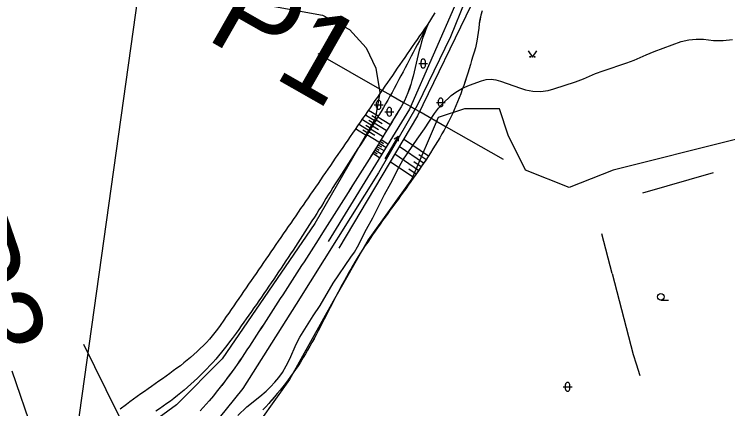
# Model space of a CAD drawing. Extents: x -737422 to -734235, y -1145631 to -1142623.
# Drawn here: x -736890.5 to -736808.9, y -1144790.3 to -1144745.2 of the extents above; entities that cross this region are included whole.
import ezdxf

# ---------------------------------------------------------------- set-up
doc = ezdxf.new("R2010")
doc.units = 0
for name, color, linetype in [('Vrstva 1', 7, 'Continuous'), ('Vrstva 2', 7, 'Continuous'), ('Vrstva 20', 7, 'Continuous'), ('Vrstva 21', 7, 'Continuous'), ('Vrstva 3', 7, 'Continuous'), ('Vrstva 30', 7, 'Continuous'), ('Vrstva 8', 7, 'Continuous'), ('Vrstva 9', 7, 'Continuous')]:
    doc.layers.add(name, color=color, linetype=linetype)

# ---------------------------------------------------------------- blocks, each defined once
blk = doc.blocks.new('3.140')
at = {"layer": 'Vrstva 1'}
blk.add_lwpolyline([(-1, 1.5), (0, 0), (1, 1.5)], dxfattribs=at)
for centre in [(-0.5, 0.1), (0.5, 0.1)]:
    blk.add_circle(centre, 0.1, dxfattribs=at)
blk = doc.blocks.new('3.040')
at = {"layer": 'Vrstva 1'}
blk.add_line((0, -0.75), (1.75, -0.75), dxfattribs=at)
blk.add_circle((0, 0), 0.75, dxfattribs=at)
blk = doc.blocks.new('3.160')
at = {"layer": 'Vrstva 1'}
for p, q in [((-1, 0), (1, 0)), ((-0.5, -0.5), (-0.5, 0.5)), ((0.5, -0.5), (0.5, 0.5))]:
    blk.add_line(p, q, dxfattribs=at)
for centre, start, end in [((0, 0.5), 0, 180), ((0, -0.5), 180, 360)]:
    blk.add_arc(centre, 0.5, start, end, dxfattribs=at)
blk = doc.blocks.new('8.021')
at = {"layer": 'Vrstva 1'}
blk.add_line((-3, 0), (3, 0), dxfattribs=at)
blk.add_lwpolyline([(2, 0.5), (3, 0), (2, -0.5)], dxfattribs=at)

msp = doc.modelspace()

# ---------------------------------------------------------------- linework, layer by layer
at = {"layer": 'Vrstva 1'}
for points in [[(-736865.99, -1144743.29), (-736855.23, -1144745.29), (-736852.15, -1144746.93), (-736850.23, -1144749.03), (-736849.12, -1144751.35), (-736848.67, -1144754.12), (-736849.21, -1144757.15), (-736856.11, -1144769.14), (-736866.72, -1144784.6), (-736871.93, -1144789.89), (-736877.86, -1144794.22), (-736879.95, -1144795.31), (-736879.05, -1144799.66), (-736881.65, -1144806.19), (-736880.62, -1144808.86), (-736878.14, -1144810.85), (-736867.34, -1144816.58), (-736863.13, -1144818.44), (-736852.07, -1144823.23), (-736841.91, -1144827.1), (-736835.16, -1144828.62)], [(-736841.958, -1144755.927), (-736841.49, -1144755.415), (-736840.497, -1144754.486), (-736839.971, -1144754.075), (-736839.207, -1144753.627), (-736838.407, -1144753.27), (-736837.061, -1144752.783), (-736836.51, -1144752.651), (-736835.949, -1144752.612), (-736835.392, -1144752.669), (-736834.85, -1144752.814), (-736832.597, -1144753.649), (-736832.009, -1144753.839), (-736831.168, -1144753.986), (-736830.29, -1144754.004), (-736829.415, -1144753.89), (-736828.777, -1144753.719), (-736826.294, -1144752.913), (-736825.368, -1144752.563), (-736824.008, -1144751.964), (-736823.144, -1144751.637), (-736820.437, -1144750.747), (-736819.574, -1144750.414), (-736818.219, -1144749.798), (-736817.297, -1144749.428), (-736814.203, -1144748.304), (-736813.338, -1144748.111), (-736812.473, -1144748.025), (-736811.647, -1144748.035), (-736810.514, -1144748.159), (-736809.955, -1144748.186), (-736809.405, -1144748.166), (-736808.351, -1144748.044)], [(-736864.924, -1144791.087), (-736863.9, -1144790.104), (-736862.389, -1144788.939), (-736861.659, -1144788.332), (-736861.16, -1144787.829), (-736860.689, -1144787.297), (-736860.232, -1144786.753), (-736859.807, -1144786.176), (-736859.365, -1144785.416), (-736858.977, -1144784.602), (-736858.242, -1144782.934), (-736857.837, -1144782.138), (-736856.286, -1144779.686), (-736855.478, -1144778.493), (-736854.01, -1144775.958), (-736851.973, -1144772.99), (-736851.575, -1144772.387), (-736851.238, -1144771.802), (-736850.188, -1144769.767), (-736849.46, -1144768.49), (-736848.146, -1144765.79), (-736847.42, -1144764.506), (-736846.429, -1144762.56), (-736846.036, -1144761.866), (-736844.41, -1144759.464), (-736843.563, -1144758.302), (-736842.415, -1144756.536), (-736841.958, -1144755.927)]]:
    msp.add_lwpolyline(points, dxfattribs=at)
at = {"layer": 'Vrstva 2'}
msp.add_lwpolyline([(-736838.94, -1144743.71), (-736840.58, -1144747.75), (-736844.39, -1144755.61), (-736848.81, -1144763.32), (-736858.24, -1144778.35), (-736864.33, -1144788), (-736868, -1144792.54), (-736868.74, -1144793.25), (-736870.42, -1144794.38), (-736872.26, -1144795.22), (-736876.13, -1144796.44), (-736887.1, -1144799.6), (-736890.46, -1144800.61), (-736895.84, -1144803.1), (-736899.26, -1144804.04), (-736901.02, -1144804.24), (-736906.35, -1144804.39), (-736912.33, -1144804.46), (-736917.21, -1144803.72), (-736923.41, -1144802.63), (-736927.55, -1144801.53), (-736932.98, -1144799.76), (-736935.72, -1144798.99), (-736947.76, -1144796.51)], dxfattribs=at)
at = {"layer": 'Vrstva 20'}
for points in [[(-736839.85, -1144743.69), (-736845.28, -1144756.03)], [(-736838.21, -1144744.12), (-736844.35, -1144756.78)], [(-736836.95, -1144744.79), (-736837.1, -1144745.27), (-736837.21, -1144745.75), (-736837.3, -1144746.25), (-736837.36, -1144746.75), (-736837.42, -1144747.25), (-736837.49, -1144747.75), (-736837.56, -1144748.25), (-736837.74, -1144749.02), (-736837.88, -1144749.5), (-736838.02, -1144749.98), (-736838.17, -1144750.46), (-736838.31, -1144750.94), (-736838.46, -1144751.42), (-736838.61, -1144751.9), (-736838.76, -1144752.37), (-736838.92, -1144752.85), (-736839.08, -1144753.32), (-736839.24, -1144753.79), (-736839.41, -1144754.27), (-736839.59, -1144754.73), (-736839.77, -1144755.2), (-736839.96, -1144755.66), (-736840.16, -1144756.12), (-736840.36, -1144756.58), (-736840.58, -1144757.03), (-736840.8, -1144757.48), (-736841.07, -1144757.99), (-736841.31, -1144758.43), (-736841.56, -1144758.87), (-736841.82, -1144759.31), (-736842.07, -1144759.74), (-736842.34, -1144760.17), (-736842.6, -1144760.59), (-736842.87, -1144761.02), (-736843.14, -1144761.44), (-736843.42, -1144761.86), (-736843.7, -1144762.27), (-736843.98, -1144762.69), (-736844.27, -1144763.1), (-736844.55, -1144763.51), (-736844.84, -1144763.92), (-736845.13, -1144764.33), (-736845.42, -1144764.74), (-736845.71, -1144765.14), (-736846.01, -1144765.55), (-736846.3, -1144765.95), (-736846.59, -1144766.36), (-736846.89, -1144766.76), (-736847.18, -1144767.17), (-736847.48, -1144767.57), (-736847.77, -1144767.98), (-736848.06, -1144768.38), (-736848.35, -1144768.79), (-736848.64, -1144769.19), (-736848.93, -1144769.6), (-736849.21, -1144770.01), (-736849.5, -1144770.42), (-736849.78, -1144770.83), (-736850.06, -1144771.24), (-736850.33, -1144771.66), (-736850.6, -1144772.08), (-736850.87, -1144772.49), (-736851.14, -1144772.92), (-736851.49, -1144773.49), (-736851.75, -1144773.92), (-736852, -1144774.35), (-736852.24, -1144774.78), (-736852.48, -1144775.22), (-736852.72, -1144775.65), (-736852.96, -1144776.09), (-736853.19, -1144776.53), (-736853.42, -1144776.98), (-736853.65, -1144777.42), (-736853.88, -1144777.86), (-736854.11, -1144778.31), (-736854.34, -1144778.75), (-736854.56, -1144779.2), (-736854.79, -1144779.64), (-736855.02, -1144780.09), (-736855.25, -1144780.53), (-736855.48, -1144780.98), (-736855.71, -1144781.42)], [(-736842.37, -1144745.01), (-736842.65, -1144745.43), (-736842.99, -1144746), (-736843.21, -1144746.45), (-736843.41, -1144746.91), (-736843.58, -1144747.37), (-736843.75, -1144747.84), (-736843.89, -1144748.32), (-736844.03, -1144748.81), (-736844.16, -1144749.3), (-736844.28, -1144749.79), (-736844.39, -1144750.28), (-736844.51, -1144750.78), (-736844.62, -1144751.27), (-736844.74, -1144751.76), (-736844.87, -1144752.25), (-736845, -1144752.74), (-736845.14, -1144753.22), (-736845.3, -1144753.69), (-736845.47, -1144754.16), (-736845.65, -1144754.62), (-736845.86, -1144755.07), (-736846.24, -1144755.77), (-736846.5, -1144756.2), (-736846.76, -1144756.63), (-736847.02, -1144757.05), (-736847.28, -1144757.48), (-736847.54, -1144757.91), (-736847.8, -1144758.34), (-736848.06, -1144758.76), (-736848.32, -1144759.19), (-736848.58, -1144759.62), (-736848.84, -1144760.04), (-736849.1, -1144760.47), (-736849.37, -1144760.89), (-736849.63, -1144761.32), (-736849.89, -1144761.74), (-736850.15, -1144762.17), (-736850.42, -1144762.59), (-736850.68, -1144763.02), (-736850.95, -1144763.44), (-736851.21, -1144763.86), (-736851.48, -1144764.29), (-736851.74, -1144764.71), (-736852.01, -1144765.14), (-736852.28, -1144765.56), (-736852.54, -1144765.98), (-736852.81, -1144766.4), (-736853.08, -1144766.83), (-736853.34, -1144767.25), (-736853.61, -1144767.67), (-736853.88, -1144768.09), (-736854.15, -1144768.52), (-736854.42, -1144768.94), (-736854.68, -1144769.36), (-736854.95, -1144769.78), (-736855.22, -1144770.2), (-736855.72, -1144770.98), (-736855.99, -1144771.4), (-736856.26, -1144771.82), (-736856.53, -1144772.24), (-736856.8, -1144772.66), (-736857.07, -1144773.09), (-736857.34, -1144773.51), (-736857.61, -1144773.93), (-736857.88, -1144774.35), (-736858.15, -1144774.77), (-736858.42, -1144775.19), (-736858.69, -1144775.61), (-736858.97, -1144776.03), (-736859.24, -1144776.45), (-736859.51, -1144776.87), (-736859.78, -1144777.29), (-736860.05, -1144777.71), (-736860.32, -1144778.13), (-736860.59, -1144778.55), (-736860.86, -1144778.97), (-736861.14, -1144779.39), (-736861.41, -1144779.81), (-736861.68, -1144780.23), (-736861.95, -1144780.65)], [(-736842.99, -1144746), (-736843.27, -1144746.41), (-736843.56, -1144746.82), (-736843.84, -1144747.24), (-736844.12, -1144747.65), (-736844.41, -1144748.06), (-736844.69, -1144748.47), (-736844.97, -1144748.88), (-736845.26, -1144749.3), (-736845.54, -1144749.71), (-736845.82, -1144750.12), (-736846.11, -1144750.53), (-736846.39, -1144750.94), (-736846.67, -1144751.36), (-736846.96, -1144751.77), (-736847.24, -1144752.18), (-736847.53, -1144752.59), (-736847.81, -1144753), (-736848.09, -1144753.42), (-736848.38, -1144753.83), (-736848.66, -1144754.24), (-736848.94, -1144754.65), (-736849.23, -1144755.06), (-736849.51, -1144755.47), (-736849.79, -1144755.89), (-736850.08, -1144756.3), (-736850.36, -1144756.71), (-736850.64, -1144757.12), (-736850.93, -1144757.53), (-736851.21, -1144757.95), (-736851.49, -1144758.36), (-736851.78, -1144758.77), (-736852.06, -1144759.18), (-736852.34, -1144759.59), (-736852.63, -1144760.01), (-736852.91, -1144760.42), (-736853.19, -1144760.83), (-736853.48, -1144761.24), (-736853.76, -1144761.65), (-736854.04, -1144762.07), (-736854.33, -1144762.48), (-736854.61, -1144762.89), (-736854.89, -1144763.3), (-736855.18, -1144763.71), (-736855.46, -1144764.13), (-736855.74, -1144764.54), (-736856.03, -1144764.95), (-736856.31, -1144765.36), (-736856.59, -1144765.77), (-736856.88, -1144766.18), (-736857.16, -1144766.6), (-736857.44, -1144767.01), (-736857.73, -1144767.42), (-736858.01, -1144767.83), (-736858.29, -1144768.24), (-736858.58, -1144768.66), (-736858.86, -1144769.07), (-736859.14, -1144769.48), (-736859.43, -1144769.89), (-736859.71, -1144770.3), (-736860, -1144770.72), (-736860.28, -1144771.13), (-736860.56, -1144771.54), (-736860.85, -1144771.95), (-736861.13, -1144772.36), (-736861.41, -1144772.78), (-736861.7, -1144773.19), (-736861.98, -1144773.6), (-736862.26, -1144774.01), (-736862.55, -1144774.42), (-736862.83, -1144774.83), (-736863.11, -1144775.25), (-736863.4, -1144775.66), (-736863.68, -1144776.07), (-736863.96, -1144776.48), (-736864.25, -1144776.89), (-736864.53, -1144777.31), (-736864.81, -1144777.72), (-736865.1, -1144778.13), (-736865.38, -1144778.54), (-736865.66, -1144778.95), (-736865.95, -1144779.37), (-736866.23, -1144779.78), (-736866.51, -1144780.19), (-736866.94, -1144780.81), (-736867.23, -1144781.22), (-736867.53, -1144781.61), (-736867.85, -1144782), (-736868.17, -1144782.37), (-736868.5, -1144782.74), (-736868.85, -1144783.1)], [(-736842.99, -1144746), (-736843.22, -1144746.44), (-736843.46, -1144746.89), (-736843.69, -1144747.33), (-736843.92, -1144747.77), (-736844.15, -1144748.21), (-736844.39, -1144748.66), (-736844.62, -1144749.1), (-736844.85, -1144749.54), (-736845.09, -1144749.98), (-736845.32, -1144750.43), (-736845.55, -1144750.87), (-736845.78, -1144751.31), (-736846.02, -1144751.75), (-736846.25, -1144752.2), (-736846.48, -1144752.64), (-736846.8, -1144753.24), (-736847.03, -1144753.68), (-736847.27, -1144754.12), (-736847.51, -1144754.56), (-736847.76, -1144755), (-736848.01, -1144755.43), (-736848.26, -1144755.86), (-736848.52, -1144756.29), (-736848.77, -1144756.72), (-736849.03, -1144757.15), (-736849.29, -1144757.57), (-736849.56, -1144758), (-736849.82, -1144758.42), (-736850.09, -1144758.84), (-736850.36, -1144759.27), (-736850.63, -1144759.69), (-736850.9, -1144760.11), (-736851.17, -1144760.53), (-736851.44, -1144760.95), (-736851.71, -1144761.37), (-736851.98, -1144761.79), (-736852.25, -1144762.21), (-736852.52, -1144762.63), (-736852.79, -1144763.05), (-736853.06, -1144763.48), (-736853.33, -1144763.9), (-736853.76, -1144764.59), (-736854.03, -1144765.01), (-736854.29, -1144765.43), (-736854.56, -1144765.86), (-736854.83, -1144766.28), (-736855.09, -1144766.7), (-736855.36, -1144767.13), (-736855.63, -1144767.55), (-736855.89, -1144767.97), (-736856.16, -1144768.39), (-736856.43, -1144768.81), (-736856.7, -1144769.23), (-736856.97, -1144769.65), (-736857.24, -1144770.07), (-736857.51, -1144770.49), (-736857.78, -1144770.91), (-736858.05, -1144771.33), (-736858.32, -1144771.74), (-736858.6, -1144772.16), (-736858.87, -1144772.58), (-736859.15, -1144773), (-736859.42, -1144773.41), (-736859.7, -1144773.83), (-736859.97, -1144774.24), (-736860.25, -1144774.66), (-736860.53, -1144775.07), (-736860.81, -1144775.49), (-736861.09, -1144775.9), (-736861.37, -1144776.31), (-736861.65, -1144776.73), (-736861.93, -1144777.14), (-736862.21, -1144777.55), (-736862.5, -1144777.96), (-736862.78, -1144778.38), (-736863.07, -1144778.79), (-736863.36, -1144779.2), (-736863.65, -1144779.61), (-736863.94, -1144780.02), (-736864.23, -1144780.43), (-736864.52, -1144780.84), (-736864.81, -1144781.25), (-736865.11, -1144781.66), (-736865.55, -1144782.27), (-736865.85, -1144782.68), (-736866.16, -1144783.08), (-736866.47, -1144783.48), (-736866.79, -1144783.87), (-736867.11, -1144784.26), (-736867.44, -1144784.64)], [(-736845.28, -1144756.03), (-736854.59, -1144771.17)], [(-736844.35, -1144756.78), (-736853.37, -1144771.93)], [(-736810.56, -1144763.31), (-736818.63, -1144765.64)], [(-736822.08, -1144774.86), (-736823.29, -1144770.3)], [(-736822.08, -1144774.86), (-736819.68, -1144784.13)], [(-736861.95, -1144780.65), (-736862.22, -1144781.06), (-736862.5, -1144781.48), (-736862.77, -1144781.9), (-736863.04, -1144782.32), (-736863.31, -1144782.74), (-736863.59, -1144783.16), (-736863.87, -1144783.6), (-736864.14, -1144784.02), (-736864.42, -1144784.43), (-736864.7, -1144784.84), (-736864.98, -1144785.25), (-736865.27, -1144785.66), (-736865.56, -1144786.06), (-736865.85, -1144786.47), (-736866.15, -1144786.87), (-736866.45, -1144787.26), (-736866.76, -1144787.66), (-736867.07, -1144788.06), (-736867.38, -1144788.45), (-736867.7, -1144788.84), (-736868.19, -1144789.43), (-736868.52, -1144789.82), (-736868.87, -1144790.2), (-736869.22, -1144790.57)], [(-736855.71, -1144781.42), (-736855.95, -1144781.86), (-736856.19, -1144782.31), (-736856.43, -1144782.74), (-736856.68, -1144783.18), (-736856.93, -1144783.62), (-736857.18, -1144784.05), (-736857.44, -1144784.48), (-736857.75, -1144784.98), (-736858.02, -1144785.4), (-736858.3, -1144785.82), (-736858.58, -1144786.23), (-736858.87, -1144786.64), (-736859.17, -1144787.04), (-736859.47, -1144787.43), (-736859.77, -1144787.83), (-736860.08, -1144788.21), (-736860.4, -1144788.6), (-736860.72, -1144788.98), (-736861.04, -1144789.35), (-736861.37, -1144789.73), (-736861.71, -1144790.1), (-736862.04, -1144790.46)], [(-736868.85, -1144783.1), (-736869.2, -1144783.44), (-736869.56, -1144783.79), (-736869.93, -1144784.12), (-736870.31, -1144784.45), (-736870.7, -1144784.77), (-736871.09, -1144785.08), (-736871.48, -1144785.4), (-736871.88, -1144785.7), (-736872.29, -1144786), (-736872.69, -1144786.3), (-736873.11, -1144786.6), (-736873.52, -1144786.89), (-736873.93, -1144787.19), (-736874.35, -1144787.48), (-736874.77, -1144787.77), (-736875.18, -1144788.06), (-736875.6, -1144788.35), (-736876.02, -1144788.64), (-736876.43, -1144788.93), (-736876.84, -1144789.23), (-736877.25, -1144789.52), (-736877.65, -1144789.83), (-736878.37, -1144790.38)], [(-736867.44, -1144784.64), (-736867.78, -1144785.02), (-736868.12, -1144785.39), (-736868.47, -1144785.76), (-736868.82, -1144786.13), (-736869.18, -1144786.48), (-736869.54, -1144786.84), (-736869.91, -1144787.18), (-736870.28, -1144787.52), (-736870.66, -1144787.86), (-736871.05, -1144788.19), (-736871.43, -1144788.51), (-736871.83, -1144788.83), (-736872.23, -1144789.14), (-736872.63, -1144789.45), (-736873.04, -1144789.74), (-736873.45, -1144790.03), (-736873.86, -1144790.32), (-736874.28, -1144790.6)], [(-736819.68, -1144784.13), (-736819.36, -1144785.18)], [(-736819.36, -1144785.18), (-736818.95, -1144786.52)]]:
    msp.add_lwpolyline(points, dxfattribs=at)
at = {"layer": 'Vrstva 21'}
for points in [[(-736848.85, -1144756.85), (-736849.96, -1144756.17)], [(-736849.2, -1144757.4), (-736850.3, -1144756.72)], [(-736849.03, -1144757.13), (-736849.58, -1144756.79)], [(-736848.89, -1144756.91), (-736847.53, -1144757.75)], [(-736849.88, -1144758.51), (-736850.99, -1144757.82)], [(-736849.54, -1144757.96), (-736850.65, -1144757.27)], [(-736849.71, -1144758.23), (-736850.27, -1144757.89)], [(-736849.37, -1144757.68), (-736849.92, -1144757.34)], [(-736849.52, -1144757.93), (-736848.84, -1144758.35)], [(-736849.31, -1144757.59), (-736847.95, -1144758.43)], [(-736849.1, -1144757.25), (-736848.42, -1144757.67)], [(-736850.23, -1144759.06), (-736851.33, -1144758.37)], [(-736850.06, -1144758.78), (-736850.61, -1144758.44)], [(-736849.94, -1144758.6), (-736849.26, -1144759.03)], [(-736849.73, -1144758.27), (-736848.37, -1144759.11)], [(-736850.15, -1144758.94), (-736848.8, -1144759.79)], [(-736848.52, -1144759.52), (-736847.74, -1144760)], [(-736843.12, -1144761.4), (-736845.95, -1144759.46)], [(-736849, -1144760.3), (-736848.22, -1144760.78)], [(-736848.88, -1144760.1), (-736848.49, -1144760.35)], [(-736848.76, -1144759.91), (-736847.98, -1144760.39)], [(-736848.64, -1144759.71), (-736848.25, -1144759.95)], [(-736843.68, -1144762.22), (-736846.46, -1144760.32)], [(-736849.48, -1144761.08), (-736848.7, -1144761.57)], [(-736849.36, -1144760.89), (-736848.97, -1144761.13)], [(-736849.24, -1144760.69), (-736848.46, -1144761.17)], [(-736849.12, -1144760.5), (-736848.73, -1144760.74)], [(-736844.24, -1144763.05), (-736846.97, -1144761.19)], [(-736843.4, -1144761.81), (-736844.22, -1144761.25)], [(-736844.81, -1144763.87), (-736847.49, -1144762.05)], [(-736843.96, -1144762.64), (-736844.79, -1144762.07)], [(-736844.53, -1144763.46), (-736845.35, -1144762.9)]]:
    msp.add_lwpolyline(points, dxfattribs=at)
at = {"layer": 'Vrstva 3'}
for points in [[(-736836.951, -1144744.794), (-736837.102, -1144745.265), (-736837.214, -1144745.75), (-736837.297, -1144746.245), (-736837.363, -1144746.746), (-736837.422, -1144747.251), (-736837.485, -1144747.754), (-736837.563, -1144748.254), (-736837.74, -1144749.02), (-736837.882, -1144749.5), (-736838.024, -1144749.98), (-736838.167, -1144750.46), (-736838.312, -1144750.939), (-736838.458, -1144751.418), (-736838.607, -1144751.896), (-736838.759, -1144752.373), (-736838.915, -1144752.848), (-736839.075, -1144753.322), (-736839.24, -1144753.794), (-736839.41, -1144754.265), (-736839.586, -1144754.733), (-736839.769, -1144755.198), (-736839.959, -1144755.661), (-736840.157, -1144756.122), (-736840.363, -1144756.579), (-736840.578, -1144757.033), (-736840.803, -1144757.483), (-736841.07, -1144757.99), (-736841.314, -1144758.432), (-736841.562, -1144758.871), (-736841.816, -1144759.306), (-736842.073, -1144759.738), (-736842.335, -1144760.167), (-736842.601, -1144760.594), (-736842.871, -1144761.017), (-736843.144, -1144761.438), (-736843.42, -1144761.857), (-736843.699, -1144762.274), (-736843.981, -1144762.688), (-736844.265, -1144763.101), (-736844.551, -1144763.512), (-736844.839, -1144763.922), (-736845.129, -1144764.33), (-736845.42, -1144764.737), (-736845.712, -1144765.144), (-736846.005, -1144765.549), (-736846.299, -1144765.954), (-736846.593, -1144766.359), (-736846.887, -1144766.763), (-736847.181, -1144767.167), (-736847.475, -1144767.572), (-736847.768, -1144767.976), (-736848.06, -1144768.381), (-736848.351, -1144768.787), (-736848.64, -1144769.193), (-736848.928, -1144769.601), (-736849.213, -1144770.009), (-736849.497, -1144770.419), (-736849.778, -1144770.83), (-736850.056, -1144771.243), (-736850.332, -1144771.658), (-736850.604, -1144772.075), (-736850.873, -1144772.494), (-736851.138, -1144772.915), (-736851.49, -1144773.49), (-736851.745, -1144773.918), (-736851.995, -1144774.348), (-736852.241, -1144774.781), (-736852.484, -1144775.216), (-736852.723, -1144775.653), (-736852.959, -1144776.093), (-736853.192, -1144776.533), (-736853.424, -1144776.975), (-736853.654, -1144777.419), (-736853.882, -1144777.863), (-736854.11, -1144778.308), (-736854.337, -1144778.753), (-736854.564, -1144779.199), (-736854.791, -1144779.644), (-736855.02, -1144780.089), (-736855.249, -1144780.534), (-736855.481, -1144780.978), (-736855.714, -1144781.422)], [(-736842.374, -1144745.009), (-736842.652, -1144745.426), (-736842.99, -1144746), (-736843.208, -1144746.448), (-736843.405, -1144746.905), (-736843.584, -1144747.37), (-736843.745, -1144747.843), (-736843.893, -1144748.323), (-736844.03, -1144748.807), (-736844.157, -1144749.296), (-736844.277, -1144749.787), (-736844.394, -1144750.281), (-736844.508, -1144750.775), (-736844.624, -1144751.268), (-736844.742, -1144751.761), (-736844.866, -1144752.25), (-736844.998, -1144752.737), (-736845.14, -1144753.218), (-736845.295, -1144753.693), (-736845.465, -1144754.162), (-736845.653, -1144754.622), (-736845.861, -1144755.073), (-736846.24, -1144755.77), (-736846.498, -1144756.198), (-736846.757, -1144756.626), (-736847.016, -1144757.054), (-736847.275, -1144757.481), (-736847.535, -1144757.909), (-736847.795, -1144758.335), (-736848.056, -1144758.762), (-736848.317, -1144759.189), (-736848.578, -1144759.615), (-736848.84, -1144760.041), (-736849.102, -1144760.466), (-736849.365, -1144760.892), (-736849.628, -1144761.317), (-736849.891, -1144761.742), (-736850.154, -1144762.167), (-736850.418, -1144762.592), (-736850.683, -1144763.016), (-736850.947, -1144763.44), (-736851.212, -1144763.864), (-736851.477, -1144764.288), (-736851.743, -1144764.712), (-736852.009, -1144765.135), (-736852.275, -1144765.558), (-736852.541, -1144765.981), (-736852.808, -1144766.404), (-736853.075, -1144766.827), (-736853.343, -1144767.249), (-736853.611, -1144767.672), (-736853.878, -1144768.094), (-736854.147, -1144768.516), (-736854.415, -1144768.938), (-736854.684, -1144769.36), (-736854.953, -1144769.781), (-736855.222, -1144770.203), (-736855.72, -1144770.98), (-736855.99, -1144771.401), (-736856.26, -1144771.822), (-736856.53, -1144772.243), (-736856.8, -1144772.664), (-736857.071, -1144773.085), (-736857.341, -1144773.505), (-736857.611, -1144773.926), (-736857.882, -1144774.346), (-736858.153, -1144774.766), (-736858.423, -1144775.187), (-736858.694, -1144775.607), (-736858.965, -1144776.027), (-736859.236, -1144776.447), (-736859.507, -1144776.867), (-736859.778, -1144777.287), (-736860.05, -1144777.707), (-736860.321, -1144778.127), (-736860.592, -1144778.546), (-736860.864, -1144778.966), (-736861.136, -1144779.386), (-736861.407, -1144779.805), (-736861.679, -1144780.225), (-736861.951, -1144780.645)], [(-736861.951, -1144780.645), (-736862.223, -1144781.064), (-736862.495, -1144781.484), (-736862.768, -1144781.903), (-736863.04, -1144782.323), (-736863.312, -1144782.742), (-736863.585, -1144783.161), (-736863.87, -1144783.6), (-736864.144, -1144784.018), (-736864.421, -1144784.433), (-736864.701, -1144784.844), (-736864.984, -1144785.254), (-736865.27, -1144785.66), (-736865.559, -1144786.064), (-736865.853, -1144786.466), (-736866.15, -1144786.866), (-736866.451, -1144787.264), (-736866.756, -1144787.66), (-736867.066, -1144788.055), (-736867.38, -1144788.448), (-736867.699, -1144788.839), (-736868.19, -1144789.43), (-736868.524, -1144789.817), (-736868.868, -1144790.197), (-736869.223, -1144790.57)], [(-736855.714, -1144781.422), (-736855.95, -1144781.864), (-736856.188, -1144782.305), (-736856.43, -1144782.744), (-736856.676, -1144783.181), (-736856.926, -1144783.617), (-736857.18, -1144784.05), (-736857.44, -1144784.48), (-736857.75, -1144784.98), (-736858.022, -1144785.403), (-736858.3, -1144785.82), (-736858.583, -1144786.231), (-736858.873, -1144786.637), (-736859.168, -1144787.038), (-736859.468, -1144787.434), (-736859.774, -1144787.826), (-736860.084, -1144788.213), (-736860.399, -1144788.596), (-736860.719, -1144788.976), (-736861.044, -1144789.352), (-736861.372, -1144789.725), (-736861.705, -1144790.096), (-736862.042, -1144790.464)]]:
    msp.add_lwpolyline(points, dxfattribs=at)
at = {"layer": 'Vrstva 30'}
msp.add_lwpolyline([(-736794, -1144756), (-736822, -1144763), (-736827, -1144765), (-736832, -1144763), (-736834, -1144759), (-736835, -1144756), (-736839, -1144756), (-736842, -1144757), (-736845, -1144764), (-736850, -1144771), (-736854, -1144778), (-736859, -1144787), (-736864, -1144794), (-736868, -1144798), (-736873, -1144800), (-736876, -1144805), (-736874, -1144810), (-736869, -1144816), (-736870, -1144821), (-736874, -1144823), (-736879, -1144820), (-736886, -1144820), (-736894, -1144821)], dxfattribs=at)
at = {"layer": 'Vrstva 8'}
for points in [[(-736884.4, -1144800.84), (-736869.33, -1144693.23)], [(-736855.77, -1144749.68), (-736848.43, -1144753.87), (-736847.43, -1144754.42), (-736845.97, -1144755.27), (-736845.13, -1144755.74), (-736844.63, -1144756.03), (-736844.12, -1144756.31), (-736844.11, -1144756.32), (-736841.09, -1144758.04), (-736834.58, -1144761.75)], [(-736882.57, -1144782.92), (-736878.74, -1144790.67), (-736877.81, -1144792.57), (-736876.72, -1144794.8), (-736876.27, -1144795.69), (-736875.97, -1144796.27), (-736875.92, -1144796.37), (-736875.6, -1144797.03), (-736874.93, -1144798.41), (-736874.22, -1144799.85), (-736873.38, -1144801.55), (-736872.2, -1144803.94)], [(-736890.77, -1144785.98), (-736888.36, -1144793.02), (-736886.95, -1144797.15), (-736886.44, -1144798.63), (-736886.21, -1144799.34), (-736886.19, -1144799.41), (-736885.97, -1144800.03), (-736885.63, -1144801), (-736883.96, -1144805.87), (-736882.26, -1144810.82)]]:
    msp.add_lwpolyline(points, dxfattribs=at)

# ---------------------------------------------------------------- block references
at = {"layer": 'Vrstva 20', "xscale": 0.5, "yscale": 0.5}
for name, p in [('3.140', (-736831.21, -1144750.09)), ('3.160', (-736843.71, -1144750.81)), ('3.160', (-736848.8, -1144755.54)), ('3.160', (-736841.7, -1144755.26)), ('3.160', (-736847.58, -1144756.33)), ('3.040', (-736816.54, -1144777.51)), ('3.160', (-736827.19, -1144787.82))]:
    msp.add_blockref(name, p, dxfattribs=at)
at = {"layer": 'Vrstva 20', "xscale": 0.5000000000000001, "yscale": 0.4999999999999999, "rotation": 59.90254254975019}
msp.add_blockref('8.021', (-736847.3, -1144760.43), dxfattribs=at)

# ---------------------------------------------------------------- texts
at = {"layer": 'Vrstva 9'}
for s, rotation, p in [('P1', 330.322, (-736868.76, -1144747.89)), ('P3', 288.954, (-736901.1, -1144770.46))]:
    msp.add_text(s, height=10, rotation=rotation, dxfattribs=at).set_placement(p)

doc.saveas('drawing.dxf')
